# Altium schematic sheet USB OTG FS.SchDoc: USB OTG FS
size A4; CompanyName: STMicroelectronics; Organization: Microcontrollers Division; DocumentNumber: 15; SheetNumber: 7; SheetTotal: 19
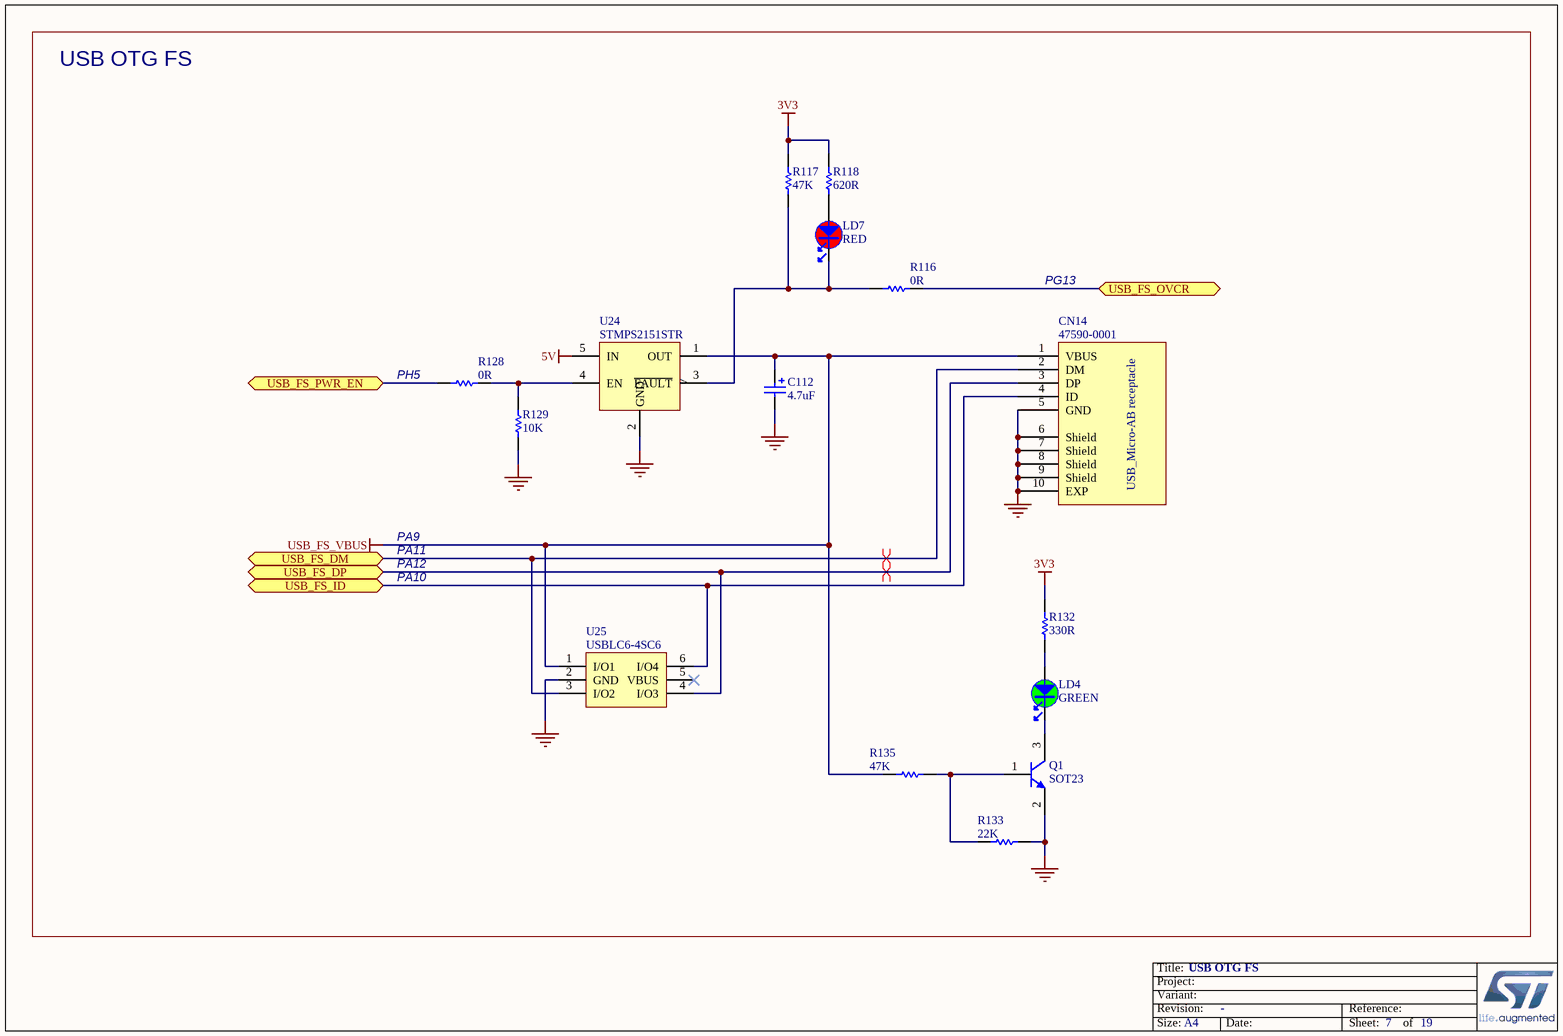
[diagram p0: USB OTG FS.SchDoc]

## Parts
C112  value 4.7uF  [CPOL_VISHAY_TANTAL-595D_1407_H220]  (hidden comment: Cap_POL_TANA)
CN14  Manufacturer_Part_Number: 47590-0001  [CON_USBMICROAB_MOLEX_47590-0001_H3]  (hidden comment: USB_uAB_47590.0001)
LD4  value GREEN  [LED_0603_GREEN]  (hidden comment: LED_green)
LD7  value RED  [LED_0603_RED]  (hidden comment: LED_red)
Q1  value SOT23  [NPN_SOT23]  (hidden comment: 9013-SOT23)
R116  value 0R  [R0402]  (hidden comment: Resistor)
R117  value 47K  [R0402]  (hidden comment: Resistor)
R118  value 620R  [R0402]  (hidden comment: Resistor)
R128  value 0R  [R0402]  (hidden comment: Resistor)
R129  value 10K  [R0402]  (hidden comment: Resistor)
R132  value 330R  [R0402]  (hidden comment: Resistor)
R133  value 22K  [R0402]  (hidden comment: Resistor)
R135  value 47K  [R0402]  (hidden comment: Resistor)
U24  STMPS2151STR  [MOS_SOT23-5L]
U25  USBLC6-4SC6  [ESD_SOT23-6L]

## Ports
USB_FS_DM, USB_FS_DP, USB_FS_ID, USB_FS_OVCR, USB_FS_PWR_EN

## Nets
3V3: R117.2 R118.2 R132.2
5V: U24.5(IN)
GND: C112.2 CN14.5(GND) CN14.6(Shield) CN14.7(Shield) CN14.8(Shield) CN14.9(Shield) CN14.10(EXP) Q1.2(E) R129.1 R133.2 U24.2(GND) U25.2(GND)
USB_FS_VBUS: C112.1 CN14.1(VBUS) R135.2 U24.1(OUT) U25.1(I/O1)
USB_FS_DM: CN14.2(DM) U25.3(I/O2) ; port USB_FS_DM
USB_FS_DP: CN14.3(DP) U25.4(I/O3) ; port USB_FS_DP
USB_FS_ID: CN14.4(ID) U25.6(I/O4) ; port USB_FS_ID
USB_FS_OVCR: R116.2 ; port USB_FS_OVCR
USB_FS_PWR_EN: R128.1 ; port USB_FS_PWR_EN
NetLD4_1: LD4.1 R132.1
NetLD4_2: LD4.2 Q1.3(C)
NetLD7_1: LD7.1 R118.1
NetLD7_2: LD7.2 R116.1 R117.1 U24.3(~{FAULT})
NetQ1_1: Q1.1(B) R133.1 R135.1
NetR128_2: R128.2 R129.2 U24.4(EN)

Not connected (* = marked no-connect by the designer): U25 5(VBUS)*

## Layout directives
differential pair: USB_FS_DM, USB_FS_DP

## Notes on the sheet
- USB OTG FS
- PG13
- (near R128) PH5
- PA9
- PA10
- PA11
- PA12

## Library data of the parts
C112 = MCD-00595: Capacitor, Tantalum, 4.7uF, 16V, +/-10%, 595D case A; Manufacturer_Part_Number: 595D475X9016A2T; Manufacturer: VISHAY; Order_Code_RS: 117-303; Provided_By: SUBCO
CN14 = MCD-00022: USB-MICRO-AB, 0.65mm, RA, SMT, Top Mount (compatible with MCD-00661 USB certified); Part_Type: Connector; Manufacturer: MOLEX; Alternate_Manufacturer_Part_Number: ZX62RD-AB-5P8(30); Alternate_Manufacturer: HIROSE; Provided_By: SUBCO
LD4 = MCD-00050: LED, Green, 0603; Part_Type: Display; Manufacturer_Part_Number: 19-213SYGC/S530-E2/TR8; Manufacturer: EVERLIGHT; Provided_By: SUBCO
LD7 = MCD-00049: LED, Red, 0603; Manufacturer_Part_Number: 19-213-R6C-AP1Q2B/3T; Manufacturer: EVERLIGHT; Part_Type: Display; Provided_By: SUBCO
Q1 = MCD-00073: NPN Bipolar Transistor; Part_Type: IC; Manufacturer_Part_Number: BSR14; Manufacturer: ON SEMICONDUCTOR; Alternate_Manufacturer_Part_Number: MMBT2222ALT1G / MMBT2222ALT3G; Provided_By: SUBCO
R116 R128 = MCD-00052: Resistor,0R,0402,5%,1/16W; Manufacturer_Part_Number: RC0402JR-070RL; Manufacturer: YAGEO; Provided_By: SUBCO
R117 R135 = MCD-00063: Resistor,47K,0402,1%,1/16W; Manufacturer_Part_Number: RC0402FR-0747KL; Manufacturer: YAGEO; Provided_By: SUBCO
R118 = MCD-00499: Resistor,620R,0402,1%,1/16W; Manufacturer_Part_Number: RC0402FR-07620RL; Manufacturer: YAGEO; Provided_By: SUBCO
R129 = MCD-00053: Resistor,10K,0402,1%,1/16W; Manufacturer_Part_Number: RC0402FR-0710KL; Manufacturer: YAGEO; Provided_By: SUBCO
R132 = MCD-00062: Resistor,330R,0402,1%,1/16W; Manufacturer_Part_Number: RC0402FR-07330RL; Manufacturer: YAGEO; Provided_By: SUBCO
R133 = MCD-00429: Resistor,22K,0402,1%,1/16W; Manufacturer_Part_Number: RC0402FR-0722KL; Manufacturer: YAGEO; Provided_By: SUBCO
U24 = MCD-00159: 500mA, Enhanced single channel power switches with active high enable pin; Part_Type: IC; Manufacturer: STMICROELECTRONICS; Alternate_Manufacturer_Part_Number: TPS2051C; Alternate_Manufacturer: TEXAS INSTRUMENTS; BMS_Part_Number: 9159009; Provided_By: SUBCO with ST control
U25 = MCD-00250: Very low capacitance ESD protection , 4 lines; Part_Type: IC; Manufacturer: STMICROELECTRONICS; BMS_Part_Number: 9151001; Provided_By: SUBCO with ST control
